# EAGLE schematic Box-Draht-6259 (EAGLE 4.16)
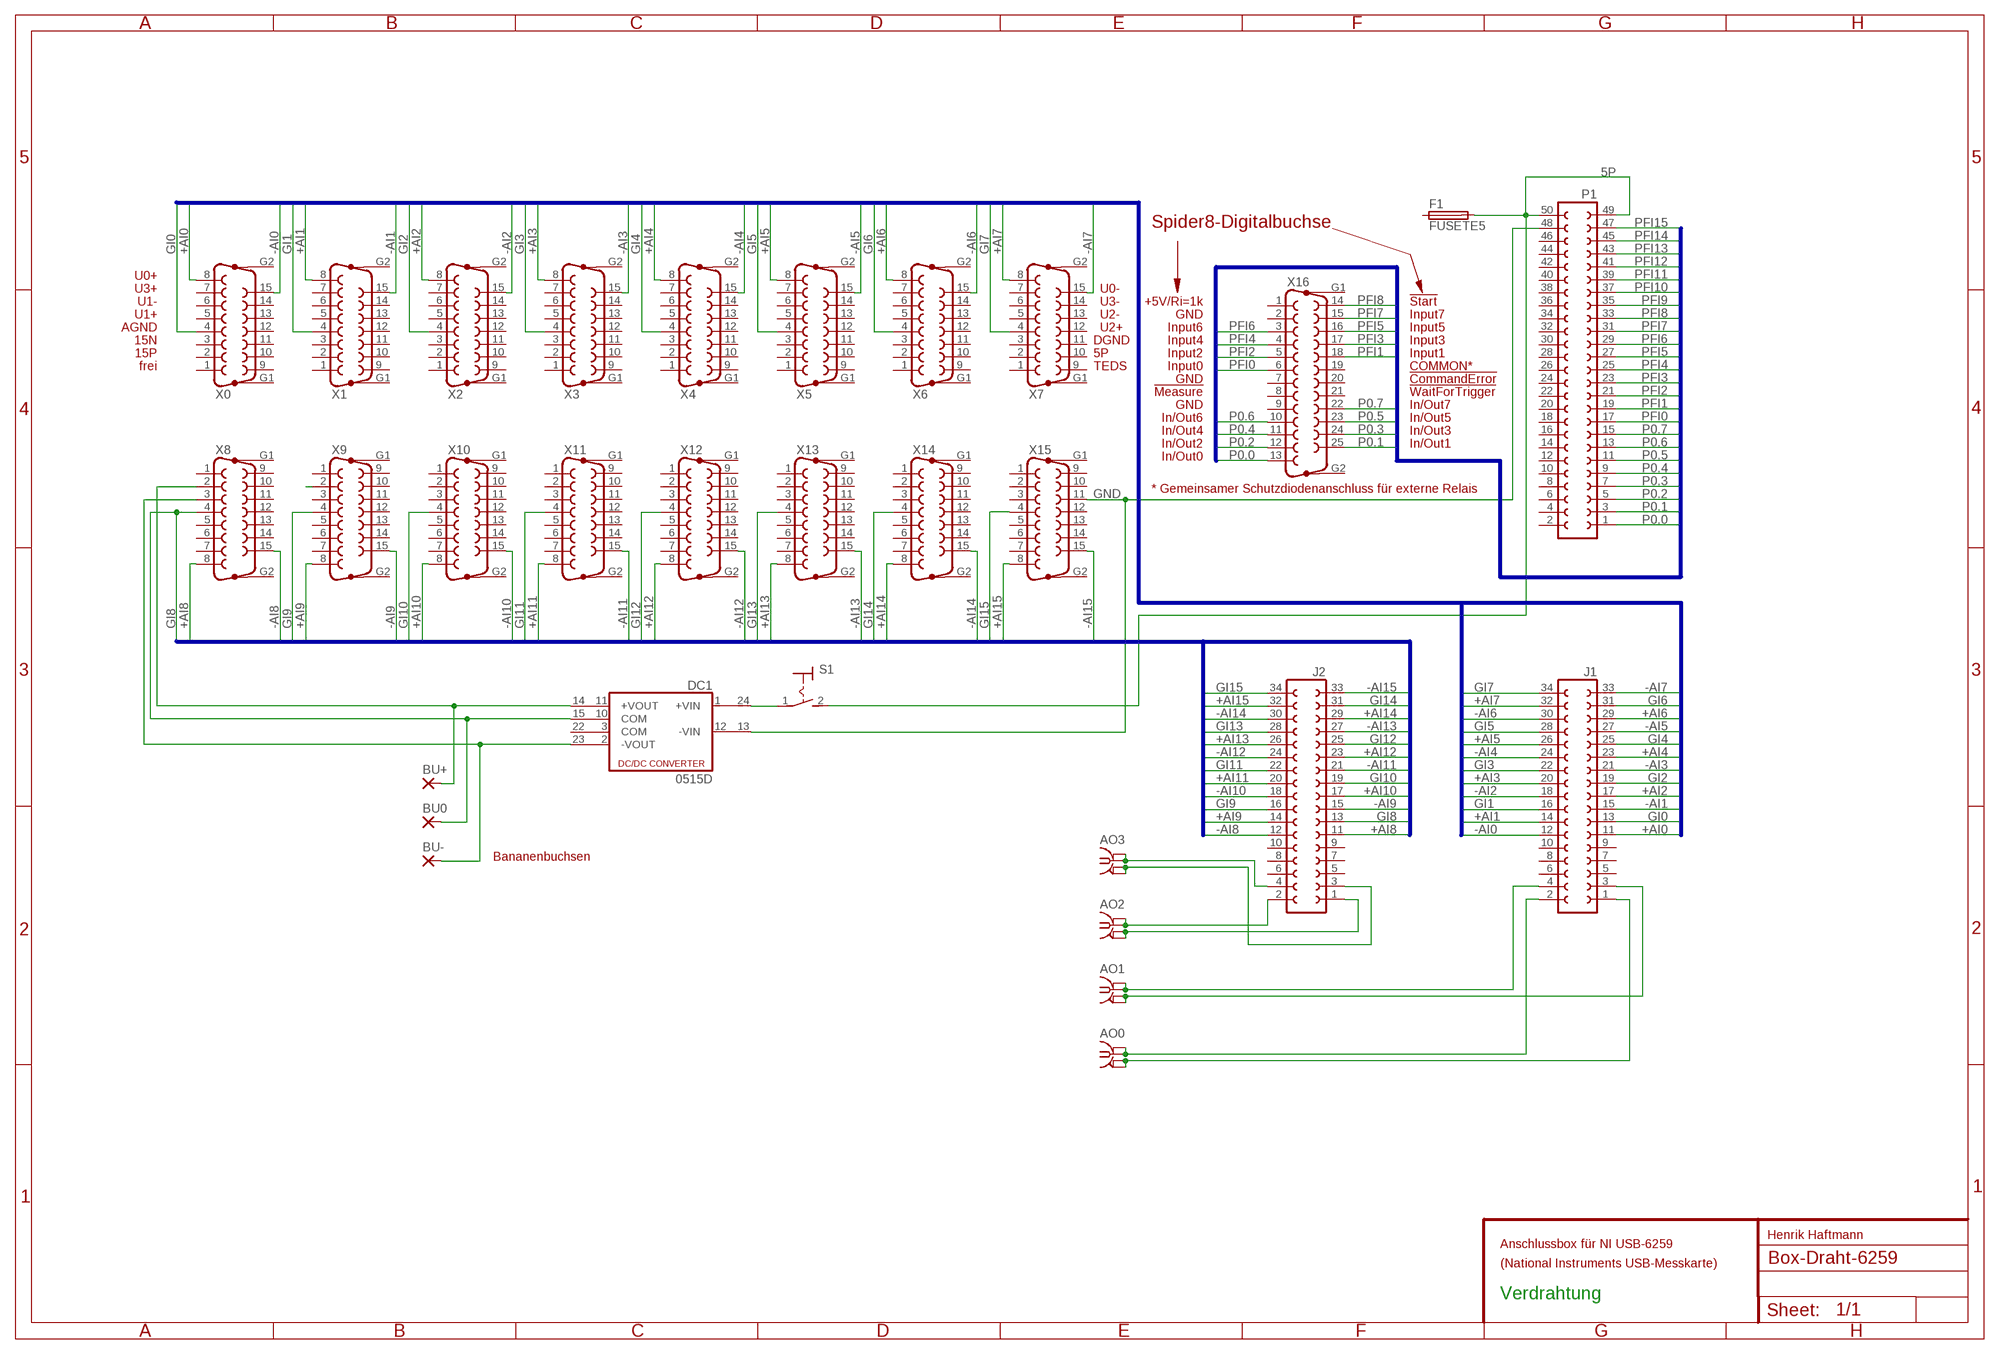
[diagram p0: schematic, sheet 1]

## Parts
AO0  BU-BNC  [BU-BNC]
AO1  BU-BNC  [BU-BNC]
AO2  BU-BNC  [BU-BNC]
AO3  BU-BNC  [BU-BNC]
BU0  2,54/1,0  [2,54/1,0]
BU+  2,54/1,0  [2,54/1,0]
BU-  2,54/1,0  [2,54/1,0]
DC1  0515D  DCW2C  [DCW]
F1  FUSETE5  [TE5]
J1  FE17-2W  [FE17-2W]
J2  FE17-2W  [FE17-2W]
P1  FE25-2  [FE25-2]
S1  MS243  [MS243]
X0  F15VP  [F15VP]
X1  F15VP  [F15VP]
X2  F15VP  [F15VP]
X3  F15VP  [F15VP]
X4  F15VP  [F15VP]
X5  F15VP  [F15VP]
X6  F15VP  [F15VP]
X7  F15VP  [F15VP]
X8  F15VP  [F15VP]
X9  F15VP  [F15VP]
X10  F15VP  [F15VP]
X11  F15VP  [F15VP]
X12  F15VP  [F15VP]
X13  F15VP  [F15VP]
X14  F15VP  [F15VP]
X15  F15VP  [F15VP]
X16  F25VP  [F25VP]

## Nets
5P: F1.2 P1.49 P1.50 S1.2(S)
+AI0: J1.11 X0.8
+AI1: J1.14 X1.8
+AI2: J1.17 X2.8
+AI3: J1.20 X3.8
+AI4: J1.23 X4.8
+AI5: J1.26 X5.8
+AI6: J1.29 X6.8
+AI7: J1.32 X7.8
+AI8: J2.11 X8.8
+AI9: J2.14 X9.8
+AI10: J2.17 X10.8
+AI11: J2.20 X11.8
+AI12: J2.23 X12.8
+AI13: J2.26 X13.8
+AI14: J2.29 X14.8
+AI15: J2.32 X15.8
-AI0: J1.12 X0.15
-AI1: J1.15 X1.15
-AI2: J1.18 X2.15
-AI3: J1.21 X3.15
-AI4: J1.24 X4.15
-AI5: J1.27 X5.15
-AI6: J1.30 X6.15
-AI7: J1.33 X7.15
-AI8: J2.12 X8.15
-AI9: J2.15 X9.15
-AI10: J2.18 X10.15
-AI11: J2.21 X11.15
-AI12: J2.24 X12.15
-AI13: J2.27 X13.15
-AI14: J2.30 X14.15
-AI15: J2.33 X15.15
GI0: J1.13 X0.4
GI1: J1.16 X1.4
GI2: J1.19 X2.4
GI3: J1.22 X3.4
GI4: J1.25 X4.4
GI5: J1.28 X5.4
GI6: J1.31 X6.4
GI7: J1.34 X7.4
GI8: BU0.1(P) DC1.15(COM1) J2.13 X8.4
GI9: J2.16 X9.4
GI10: J2.19 X10.4
GI11: J2.22 X11.4
GI12: J2.25 X12.4
GI13: J2.28 X13.4
GI14: J2.31 X14.4
GI15: J2.34 X15.4
GND: DC1.13(-VIN1) P1.48 X15.11
N$1: AO1.1 AO1.1A J1.4
N$2: DC1.24(+VIN1) S1.1(P)
N$3: AO1.2 AO1.2A J1.3
N$4: X9.2
N$5: AO0.2 AO0.2A J1.1
N$6: AO0.1 AO0.1A J1.2
N$7: AO2.1 AO2.1A J2.2
N$8: AO3.1 AO3.1A J2.4
N$9: AO2.2 AO2.2A J2.1
N$10: AO3.2 AO3.2A J2.3
N$11: BU+.1(P) DC1.14(+VOUT1) X8.2
N$13: BU-.1(P) DC1.23(-VOUT1) X8.3
P0.0: P1.1 X16.13
P0.1: P1.3 X16.25
P0.2: P1.5 X16.12
P0.3: P1.7 X16.24
P0.4: P1.9 X16.11
P0.5: P1.11 X16.23
P0.6: P1.13 X16.10
P0.7: P1.15 X16.22
PFI0: P1.17 X16.6
PFI1: P1.19 X16.18
PFI2: P1.21 X16.5
PFI3: P1.23 X16.17
PFI4: P1.25 X16.4
PFI5: P1.27 X16.16
PFI6: P1.29 X16.3
PFI7: P1.31 X16.15
PFI8: P1.33 X16.14
PFI9: P1.35
PFI10: P1.37
PFI11: P1.39
PFI12: P1.41
PFI13: P1.43
PFI14: P1.45
PFI15: P1.47
Unconnected: AO0.3 AO0.3A AO0.3B AO0.4 AO0.4A AO0.4B AO1.3 AO1.3A AO1.3B AO1.4 AO1.4A AO1.4B AO2.3 AO2.3A AO2.3B AO2.4 AO2.4A AO2.4B AO3.3 AO3.3A AO3.3B AO3.4 AO3.4A AO3.4B DC1.1(+VIN) DC1.2(-VOUT) DC1.3(COM) DC1.10(COM) DC1.11(+VOUT) DC1.12(-VIN) DC1.22(COM2) F1.1 J1.5 J1.6 J1.7 J1.8 J1.9 J1.10 J2.5 J2.6 J2.7 J2.8 J2.9 J2.10 P1.2 P1.4 P1.6 P1.8 P1.10 P1.12 P1.14 P1.16 P1.18 P1.20 P1.22 P1.24 P1.26 P1.28 P1.30 P1.32 P1.34 P1.36 P1.38 P1.40 P1.42 P1.44 P1.46 X0.1 X0.2 X0.3 X0.5 X0.6 X0.7 X0.9 X0.10 X0.11 X0.12 X0.13 X0.14 X0.G1 X0.G2 X1.1 X1.2 X1.3 X1.5 X1.6 X1.7 X1.9 X1.10 X1.11 X1.12 X1.13 X1.14 X1.G1 X1.G2 X2.1 X2.2 X2.3 X2.5 X2.6 X2.7 X2.9 X2.10 X2.11 X2.12 X2.13 X2.14 X2.G1 X2.G2 X3.1 X3.2 X3.3 X3.5 X3.6 X3.7 X3.9 X3.10 X3.11 X3.12 X3.13 X3.14 X3.G1 X3.G2 X4.1 X4.2 X4.3 X4.5 X4.6 X4.7 X4.9 X4.10 X4.11 X4.12 X4.13 X4.14 X4.G1 X4.G2 X5.1 X5.2 X5.3 X5.5 X5.6 X5.7 X5.9 X5.10 X5.11 X5.12 X5.13 X5.14 X5.G1 X5.G2 X6.1 X6.2 X6.3 X6.5 X6.6 X6.7 X6.9 X6.10 X6.11 X6.12 X6.13 X6.14 X6.G1 X6.G2 X7.1 X7.2 X7.3 X7.5 X7.6 X7.7 X7.9 X7.10 X7.11 X7.12 X7.13 X7.14 X7.G1 X7.G2 X8.1 X8.5 X8.6 X8.7 X8.9 X8.10 X8.11 X8.12 X8.13 X8.14 X8.G1 X8.G2 X9.1 X9.3 X9.5 X9.6 X9.7 X9.9 X9.10 X9.11 X9.12 X9.13 X9.14 X9.G1 X9.G2 X10.1 X10.2 X10.3 X10.5 X10.6 X10.7 X10.9 X10.10 X10.11 X10.12 X10.13 X10.14 X10.G1 X10.G2 X11.1 X11.2 X11.3 X11.5 X11.6 X11.7 X11.9 X11.10 X11.11 X11.12 X11.13 X11.14 X11.G1 X11.G2 X12.1 X12.2 X12.3 X12.5 X12.6 X12.7 X12.9 X12.10 X12.11 X12.12 X12.13 X12.14 X12.G1 X12.G2 X13.1 X13.2 X13.3 X13.5 X13.6 X13.7 X13.9 X13.10 X13.11 X13.12 X13.13 X13.14 X13.G1 X13.G2 X14.1 X14.2 X14.3 X14.5 X14.6 X14.7 X14.9 X14.10 X14.11 X14.12 X14.13 X14.14 X14.G1 X14.G2 X15.1 X15.2 X15.3 X15.5 X15.6 X15.7 X15.9 X15.10 X15.12 X15.13 X15.14 X15.G1 X15.G2 X16.1 X16.2 X16.7 X16.8 X16.9 X16.19 X16.20 X16.21 X16.G1 X16.G2

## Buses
+AI[0..7],-AI[0..7],GI[0..7]
+AI[8..15],-AI[8..15],GI[8..15]
P0.[0..7],PFI[0..15]

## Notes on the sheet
- Spider8-Digitalbuchse
- U0+
- U3+ | U0-
- U1- | U3- | +5V/Ri=1k | !Start
- U1+ | U2- | GND | Input7
- AGND | U2+ | Input6 | Input5
- 15N | DGND | Input4 | Input3
- 15P | 5P | Input2 | Input1
- frei | TEDS | Input0 | COMMON*
- GND | !CommandError
- !Measure | !WaitForTrigger
- GND | In/Out7
- In/Out6 | In/Out5
- In/Out4 | In/Out3
- In/Out2 | In/Out1
- In/Out0
- * Gemeinsamer Schutzdiodenanschluss für externe Relais
- Bananenbuchsen
- Henrik Haftmann
- Anschlussbox für NI USB-6259
- (National Instruments USB-Messkarte)
- Verdrahtung

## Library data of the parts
AO0 AO1-AO3 = Trigger-EA:BU-BNC: BNC-Buchse von Schneider
BU0 BU+ BU- = wirepad:2,54/1,0: THROUGH-HOLE PAD
DC1 = dc-dc-converter:DCW2C: DC-DC CONVERTER
F1 = fuse:FUSE: Fuse
J1 J2 = con-lsta:FE17-2W: FEMALE HEADER
P1 = con-lsta:FE25-2: FEMALE HEADER
S1 = switch:MS243: TOGGLE SWITCH
X0 X1-X15 = con-subd:F15VP: SUB-D
X16 = con-subd:F25VP: SUB-D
